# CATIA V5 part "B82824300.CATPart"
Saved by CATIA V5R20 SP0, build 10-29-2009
Part number: B82824300
Revision: 4
Definition: design
Nomenclature: B82824300
Source: made
Description: NOT SPECIFIED
Bounding box of the stored display mesh (mm): x -14 to 14, y -14 to 14, z 0 to 300
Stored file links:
  C:\Users\Raffaele\Desktop\3D X SITO CF\BOLEX\7-PILLAR REF 828\B82824300.CATPart
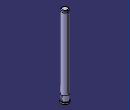
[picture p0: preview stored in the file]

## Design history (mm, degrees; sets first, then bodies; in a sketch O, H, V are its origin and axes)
Body1 "MANIFOLD_SOLID_BREP #450" (main body)
  Solid1: solid without history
